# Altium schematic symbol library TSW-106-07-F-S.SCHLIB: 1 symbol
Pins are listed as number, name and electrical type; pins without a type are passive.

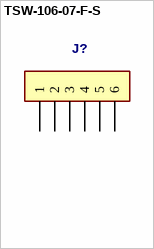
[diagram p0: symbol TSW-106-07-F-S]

## TSW-106-07-F-S
designator J?
footprint TSW-106-07-F-S
pins: 1, 2, 3, 4, 5, 6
